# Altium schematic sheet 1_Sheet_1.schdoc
size 515 x 360 mm; Name: A_Customize; Symbol: A_Customize; Device: A_Customize; @Project Name: MyOwnMP3_PCB; REV: 1.0; Date: 2026-02-21; Sheet: 1/1; Draw By: maxyusyuk; Company: Your Company; Convert to PCB: yes; Add into BOM: yes; spicePre: .; @Page No: 1; @Page Count: 3; @Schematic Name: MyOwnMP3; @Board Name: MyOwnMP3; @Update Date: 2026-04-22; @Create Time: 17:18:59; @Update Time: 22:12:06; @Page Name: Sheet_1; @Create Date: 2026-03-28
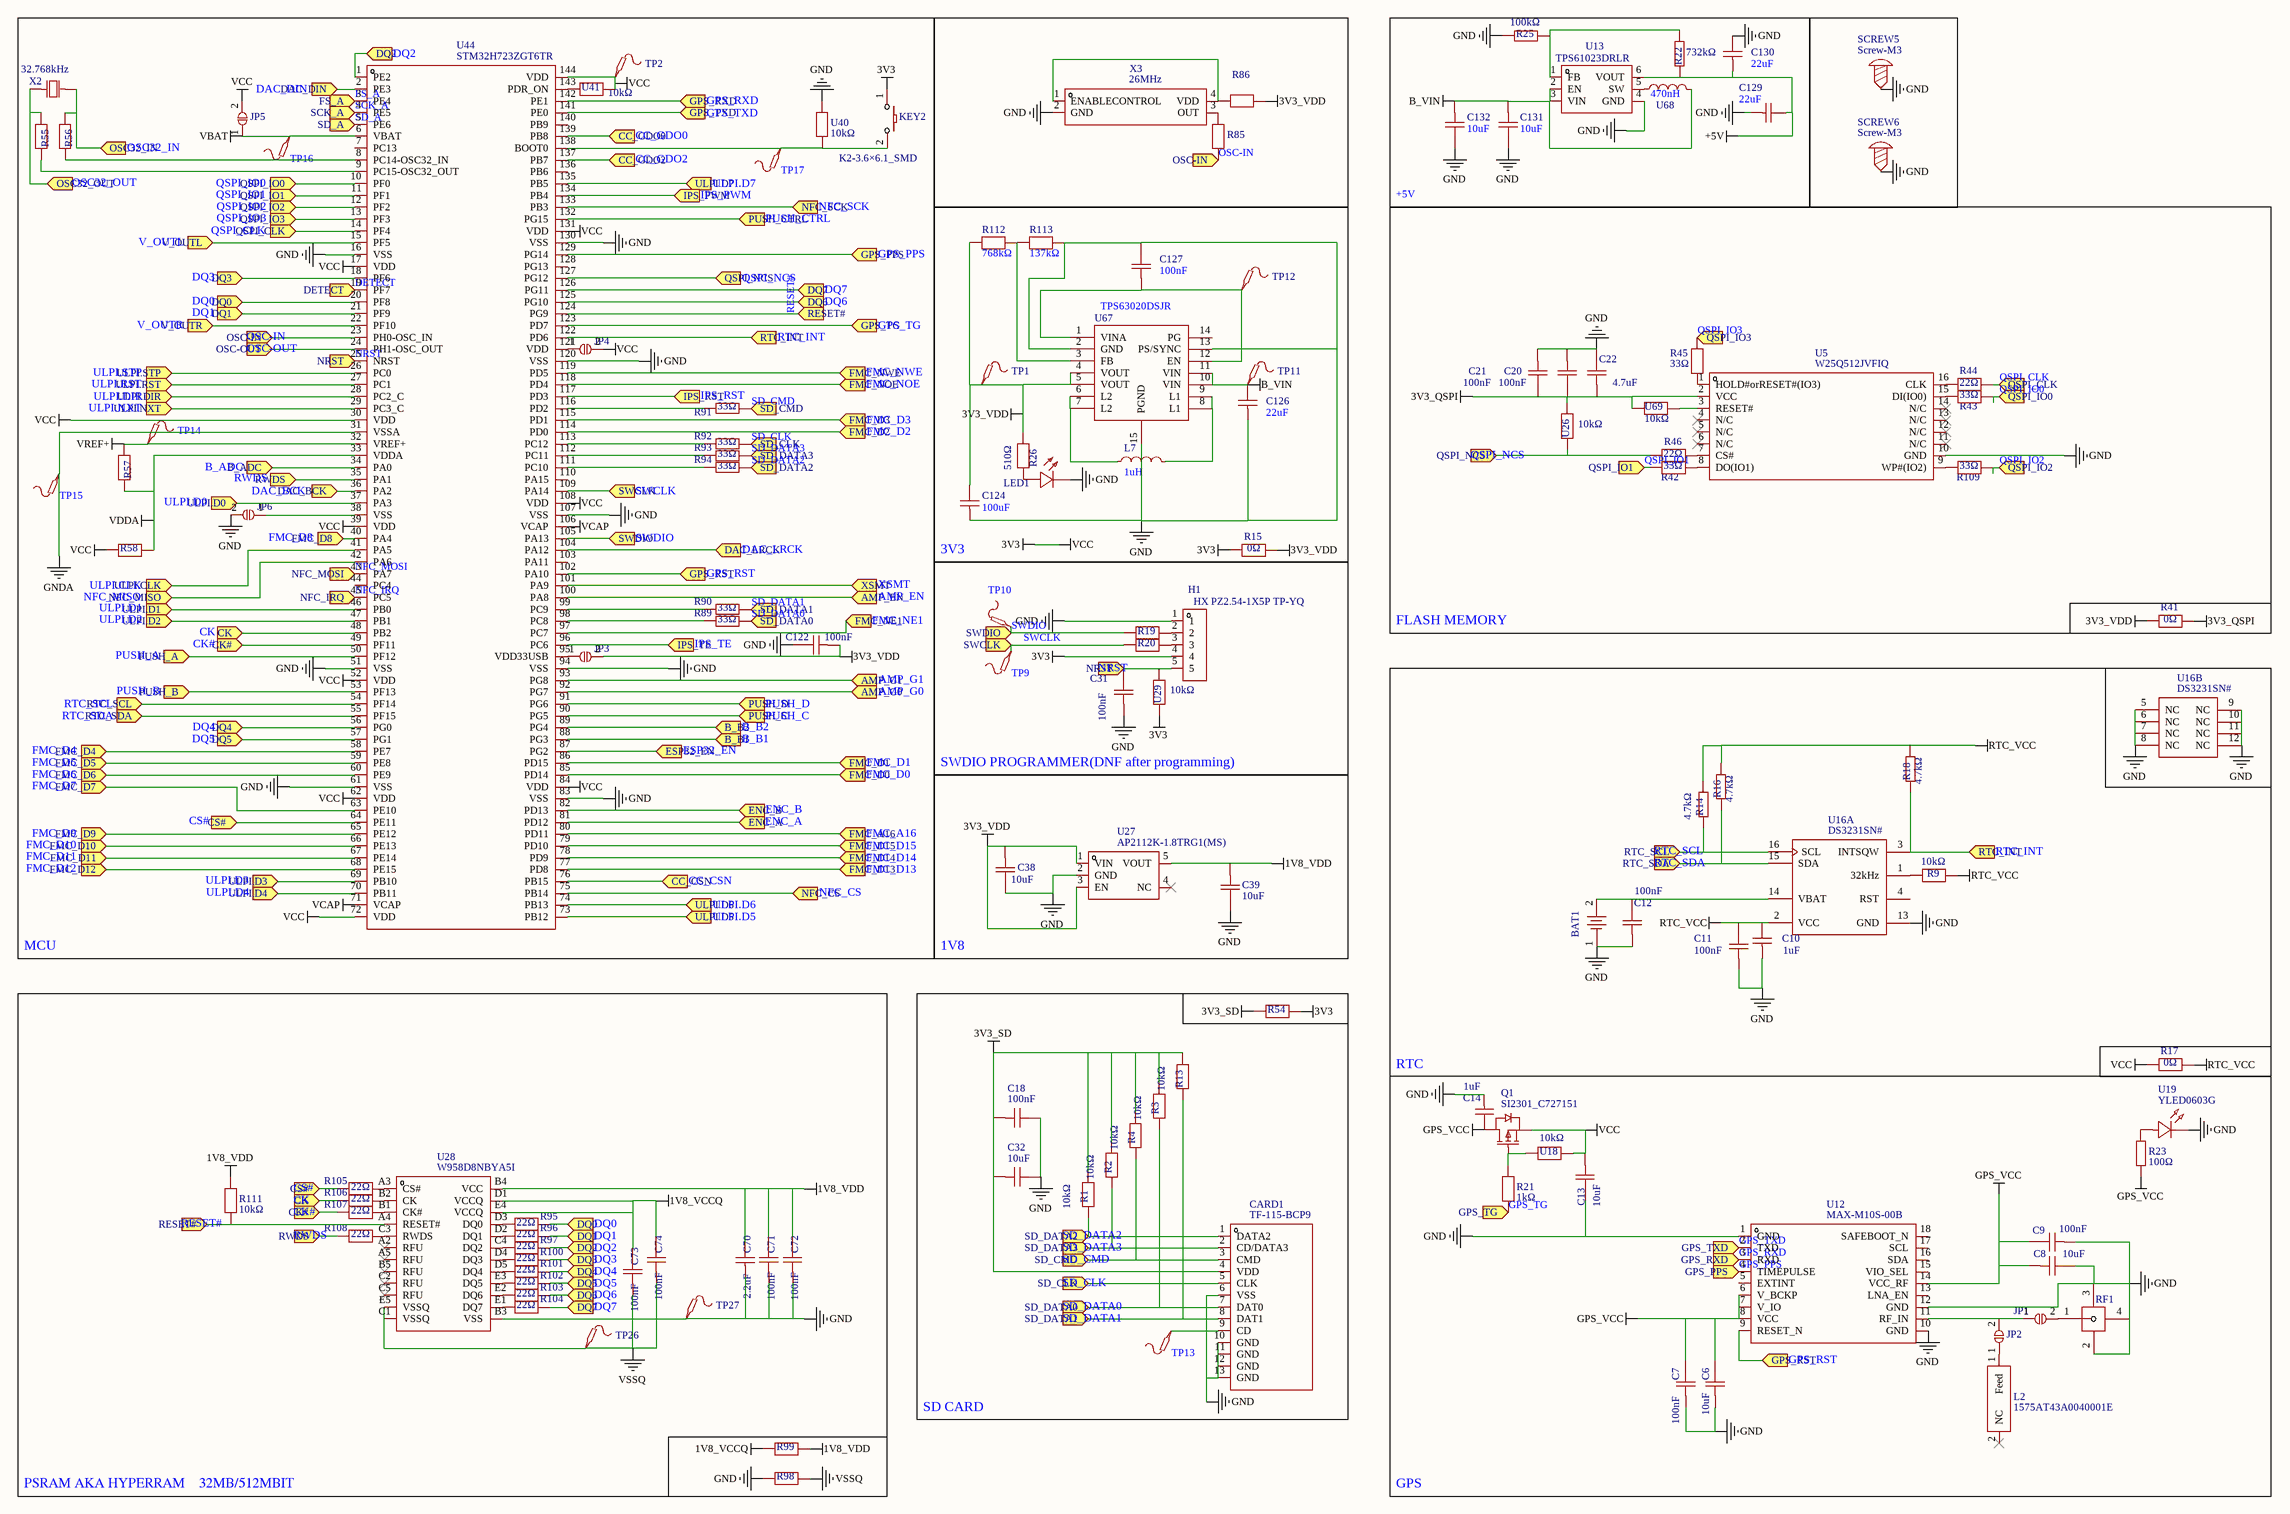
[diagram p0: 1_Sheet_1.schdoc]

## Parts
BAT1  BS-CR2032-8  [BAT-SMD_BS-CR2032-8]  (value not drawn)
C6  10uF  [C1206]
C7  100nF  [C0603]
C8  10uF  [C1206]
C9  100nF  [C0603]
C10  1uF  [C0603]
C11  100nF  [C0603]
C12  100nF  [C0603]
C13  10uF  [C1206]
C14  1uF  [C0603]
C18  100nF  [C0603]
C20  100nF  [C0603]
C21  100nF  [C0603]
C22  4.7uF  [C0603]
C31  100nF  [C0603]
C32  10uF  [C1206]
C38  10uF  [C1206]
C39  10uF  [C1206]
C70  2.2uF  [C0603]
C71  100nF  [C0603]
C72  100nF  [C0603]
C73  100nF  [C0603]
C74  100nF  [C0603]
C122  100nF  [C0603]
C124  100uF  [C1206]
C126  22uF  [C1206]
C127  100nF  [C0402]
C129  22uF  [C1206]
C130  22uF  [C1206]
C131  10uF  [C0805]
C132  10uF  [C0805]
CARD1  TF-115-BCP9  [TF-SMD_TF-115-BCP9]
H1  HX PZ2.54-1X5P TP-YQ  [HDR-SMD_5P--P2.54-V-M-S5.0_HX-PZ2.54-1X5P-TP-YQ]
JP1  2P Solder UNBridge Jumper  [SOLDER BRIDGE 2P UNBRIDGED]  (value not drawn)
JP2  2P Solder UNBridge Jumper  [SOLDER BRIDGE 2P UNBRIDGED]  (value not drawn)
JP3  2P Solder UNBridge Jumper  [SOLDER BRIDGE 2P UNBRIDGED]  (value not drawn)
JP4  2P Solder UNBridge Jumper  [SOLDER BRIDGE 2P UNBRIDGED]  (value not drawn)
JP5  2P Solder UNBridge Jumper  [SOLDER BRIDGE 2P UNBRIDGED]  (value not drawn)
JP6  2P Solder UNBridge Jumper  [SOLDER BRIDGE 2P UNBRIDGED]  (value not drawn)
KEY2  K2-3.6×6.1_SMD  [KEY-SMD_2P-L6.2-W3.6-LS8.0]
L2  1575AT43A0040001E  [ANT-SMD_L7.0-W2.0-R]
L7  1uH  [IND-SMD_L2.4-W2.4_NRH2410T]
LED1  YLED0603R  [LED0603-FD]  (value not drawn)
Q1  SI2301_C727151  [SOT-23-3_L2.9-W1.4-P1.91-LS2.6-BR]
R1  10kΩ  [R0603]
R2  10kΩ  [R0603]
R3  10kΩ  [R0603]
R4  10kΩ  [R0603]
R9  10kΩ  [R0603]
R13  10kΩ  [R0603]
R14  4.7kΩ  [R0603]
R15  0Ω  [R1206]
R16  4.7kΩ  [R0603]
R17  0Ω  [R1206]
R18  4.7kΩ  [R0603]
R19  0Ω  [R0603]  (value not drawn)
R20  0Ω  [R0603]  (value not drawn)
R21  1kΩ  [R0603]
R22  732kΩ  [R0603]
R23  100Ω  [R0603]
R25  100kΩ  [R1206]
R26  510Ω  [R0603]
R41  0Ω  [R1206]
R42  33Ω  [R0402]
R43  33Ω  [R0402]
R44  22Ω  [R0402]
R45  33Ω  [R0402]
R46  22Ω  [R0402]
R54  0Ω  [R0603]  (value not drawn)
R55  0Ω  [R0603]  (value not drawn)
R56  0Ω  [R0603]  (value not drawn)
R57  0Ω  [R0603]  (value not drawn)
R58  0Ω  [R0603]  (value not drawn)
R85  0Ω  [R0603]  (value not drawn)
R86  0Ω  [R0603]  (value not drawn)
R89  33Ω  [R0603]
R90  33Ω  [R0603]
R91  33Ω  [R0603]
R92  33Ω  [R0603]
R93  33Ω  [R0603]
R94  33Ω  [R0603]
R95  22Ω  [R0402]
R96  22Ω  [R0402]
R97  22Ω  [R0402]
R98  0Ω  [R0603]  (value not drawn)
R99  0Ω  [R0603]  (value not drawn)
R100  22Ω  [R0402]
R101  22Ω  [R0402]
R102  22Ω  [R0402]
R103  22Ω  [R0402]
R104  22Ω  [R0402]
R105  22Ω  [R0402]
R106  22Ω  [R0402]
R107  22Ω  [R0402]
R108  22Ω  [R0402]
R109  33Ω  [R0402]
R111  10kΩ  [R0603]
R112  768kΩ  [R0603]
R113  137kΩ  [R0402]
RF1  HC-RF-IPEX0303-01  [IPEX-SMD_HC-RF-IPEX0303-01]  (value not drawn)
SCREW5  Screw-M3  [SCREW-M3]
SCREW6  Screw-M3  [SCREW-M3]
TP1  (no value)  [Test-Point-0.5mm]
TP2  (no value)  [Test-Point-0.5mm]
TP9  (no value)  [Test-Point-0.5mm]
TP10  (no value)  [Test-Point-0.5mm]
TP11  (no value)  [Test-Point-0.5mm]
TP12  (no value)  [Test-Point-0.5mm]
TP13  (no value)  [Test-Point-0.5mm]
TP14  (no value)  [Test-Point-0.5mm]
TP15  (no value)  [Test-Point-0.5mm]
TP16  (no value)  [Test-Point-0.5mm]
TP17  (no value)  [Test-Point-0.5mm]
TP26  (no value)  [Test-Point-0.5mm]
TP27  (no value)  [Test-Point-0.5mm]
U5  W25Q512JVFIQ  [SOIC-16_L10.3-W7.5-P1.27-LS10.4-BL]
U12  MAX-M10S-00B  [SMD-18_L10.1-W9.7-P1.10-TL_SKG09F]
U13  TPS61023DRLR  [SOT-563_L1.6-W1.2-P0.50-LS1.6-BR]
U16  DS3231SN#  [SOIC-16_L10.3-W7.5-P1.27-LS10.3-BL]  (parts A,B of 2)
U18  10kΩ  [R0603]
U19  YLED0603G  [LED0603-FD]
U26  10kΩ  [R0603]
U27  AP2112K-1.8TRG1(MS)  [SOT-23-5_L2.9-W1.6-P0.95-LS2.8-BR]
U28  W958D8NBYA5I  [T-PBGA-24_L8.0-W6.0-P1.00-TL_MICRON_12]
U29  10kΩ  [R0603]
U40  10kΩ  [R0603]
U41  10kΩ  [R0603]
U44  STM32H723ZGT6TR  [LQFP-144_L20.0-W20.0-P0.50-LS22.0-BL]
U67  TPS63020DSJR  [VSON-14_L4.0-W3.0-P0.50-BL-EP_TI_DSJ]
U68  470nH  [IND-SMD_L2.0-W1.6]
U69  10kΩ  [R0603]
X2  32.768kHz  [OSC-SMD_L3.2-W1.5]
X3  26MHz  [OSC-SMD_4P-L5.0-W3.2-BL_SIT8103AI]

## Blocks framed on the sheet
MCU: C122 JP3-JP6 KEY2 R55-R58 R89-R94 TP2 TP14-TP17 U40 U41 U44 X2
+5V: C129-C132 R22 R25 U13 U68
3V3: C124 C126 C127 L7 LED1 R15 R26 R112 R113 TP1 TP11 TP12 U67
FLASH MEMORY: C20-C22 R41-R46 R109 U5 U26 U69
PSRAM AKA HYPERRAM  32MB/512MBIT: C70-C74 R95-R108 R111 TP26 TP27 U28
SD CARD: C18 C32 CARD1 R1-R4 R13 R54 TP13

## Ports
AMP_EN (in), AMP_G0 (in), AMP_G1 (in), B_ADC (in), B_B1 (in), B_B2 (in), CC_CSN (in), CC_GDO0 (in), CC_GDO2 (in), CK (in), CK# (in), CS# (in), DAC_BCK (in), DAC_DIN (in), DAC_LRCK (in), DETECT (in), DQ0 (in), DQ1 (in), DQ2 (in), DQ3 (in), DQ4 (in), DQ5 (in), DQ6 (in), DQ7 (in), ENC_A (in), ENC_B (in), ESP32_EN (in), FMC_A16 (in), FMC_D0 (in), FMC_D1 (in), FMC_D2 (in), FMC_D3 (in), FMC_D4 (in), FMC_D5 (in), FMC_D6 (in), FMC_D7 (in), FMC_D8 (in), FMC_D9 (in), FMC_D10 (in), FMC_D11 (in), FMC_D12 (in), FMC_D13 (in), FMC_D14 (in), FMC_D15 (in), FMC_NE1 (in), FMC_NOE (in), FMC_NWE (in), FS_A (in), GPS_PPS (in), GPS_RST (in), GPS_RXD (in), GPS_TG (in), GPS_TXD (in), IPS_PWM (in), IPS_RST (in), IPS_TE (in), NFC_CS (in), NFC_IRQ (in), NFC_MISO (in), NFC_MOSI (in), NFC_SCK (in), NRST (in), OSC32_IN (in), OSC32_OUT (in), OSC-IN (in), OSC-OUT (in), PUSH_A (in), PUSH_B (in), PUSH_C (in), PUSH_CTRL (in), PUSH_D (in), QSPI_CLK (in), QSPI_IO0 (in), QSPI_IO1 (in), QSPI_IO2 (in), QSPI_IO3 (in), QSPI_NCS (in), RESET# (in), RTC_INT (in), RTC_SCL (in), RTC_SDA (in), RWDS (in), SCK_A (in), SD_A (in), SD_CLK (in), SD_CMD (in), SD_DATA0 (in), SD_DATA1 (in), SD_DATA2 (in), SD_DATA3 (in), SWCLK (in), SWDIO (in), ULPI.CLK (in), ULPI.D0 (in), ULPI.D1 (in), ULPI.D2 (in), ULPI.D3 (in), ULPI.D4 (in), ULPI.D5 (in), ULPI.D6 (in), ULPI.D7 (in), ULPI.DIR (in), ULPI.NXT (in), ULPI.RST (in), ULPI.STP (in), V_OUTL (in), V_OUTR (in), XSMT (in)

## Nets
1V8_VCCQ: C73.1 C74.1 R99.2 U28.D1(VCCQ) U28.E4(VCCQ)
1V8_VDD: C39.2 C70.2 C71.1 C72.1 R99.1 R111.2 U27.5(VOUT) U28.B4(VCC)
3V3: C13.2 H1.4 JP4.2(B) JP5.2(B) KEY2.1 Q1.2(S) R15.1 R17.1 R54.1 R58.2 TP2.1 U18.2 U29.2 U41.2 U44.17(VDD) U44.30(VDD) U44.39(VDD) U44.52(VDD) U44.62(VDD) U44.72(VDD) U44.84(VDD) U44.108(VDD) U44.131(VDD) U44.144(VDD)  [also labelled VCC]
3V3_QSPI: C20.1 C21.1 C22.2 R41.2 U5.2(VCC) U26.1 U69.1
3V3_SD: C18.2 C32.2 CARD1.4(VDD) R1.2 R2.2 R3.2 R4.2 R13.2 R54.2
3V3_VDD: C38.2 C122.2 C124.2 JP3.2(B) R15.2 R26.1 R41.1 R86.2 R112.2 TP1.1 U27.1(VIN) U27.3(EN) U67.4(VOUT) U67.5(VOUT)
+5V: C129.2 C130.1 R22.1 U13.6(VOUT)
B_VIN: C126.2 C131.2 C132.2 TP11.1 U13.2(EN) U13.3(VIN) U67.10(VIN) U67.11(VIN) U68.2
GND: BAT1.1 C6.2 C7.2 C8.1 C9.2 C10.1 C11.2 C12.2 C13.1 C14.1 C18.1 C20.2 C21.2 C22.1 C31.2 C32.1 C38.1 C39.1 C70.1 C71.2 C72.2 C122.1 C124.1 C126.1 C127.1 C129.1 C130.2 C131.1 C132.1 CARD1.6(VSS) CARD1.10(GND) CARD1.11(GND) CARD1.12(GND) CARD1.13(GND) H1.1 JP6.2(B) LED1.2(-) R25.1 R98.2 R113.2 RF1.2 RF1.3 RF1.4 SCREW5.1 SCREW6.1 TP27.1 U5.10(GND) U12.1(GND) U12.10(GND) U12.12(GND) U13.4(GND) U16.5(NC) U16.6(NC) U16.7(NC) U16.8(NC) U16.9(NC) U16.10(NC) U16.11(NC) U16.12(NC) U16.13(GND) U19.2(-) U27.2(GND) U28.B3(VSS) U40.1 U44.16(VSS) U44.51(VSS) U44.61(VSS) U44.83(VSS) U44.94(VSS) U44.107(VSS) U44.120(VSS) U44.130(VSS) U67.2(GND) U67.13(PS/SYNC) U67.15(PGND) X3.2(GND)
GNDA: TP15.1 U44.31(VSSA)
GPS_VCC: C6.1 C7.1 C8.2 C9.1 C14.2 Q1.3(D) R23.1 U12.6(V_BCKP) U12.7(V_IO) U12.8(VCC) U12.14(VCC_RF)
RTC_VCC: C10.2 C11.1 R9.1 R14.2 R16.2 R17.2 R18.2 U16.2(VCC)
VBAT: JP5.1(A) TP16.1 U44.6(VBAT)
VCAP: U44.71(VCAP) U44.106(VCAP)
VDDA: R57.1 R58.1 U44.33(VDDA)
VREF+: R57.2 TP14.1 U44.32(VREF+)
VSSQ: C73.2 C74.2 R98.1 TP26.1 U28.C1(VSSQ) U28.E5(VSSQ)
AMP_EN: U44.100(PA8) ; port AMP_EN
AMP_G0: U44.92(PG7) ; port AMP_G0
AMP_G1: U44.93(PG8) ; port AMP_G1
B_ADC: U44.34(PA0) ; port B_ADC
B_B1: U44.88(PG3) ; port B_B1
B_B2: U44.89(PG4) ; port B_B2
CC_CSN: U44.76(PB15) ; port CC_CSN
CC_GDO0: U44.139(PB8) ; port CC_GDO0
CC_GDO2: U44.137(PB7) ; port CC_GDO2
CK: R106.1 U44.48(PB2) ; port CK
CK#: R107.1 U44.49(PF11) ; port CK#
CS#: R105.1 U44.64(PE11) ; port CS#
DAC_BCK: U44.36(PA2) ; port DAC_BCK
DAC_DIN: U44.2(PE3) ; port DAC_DIN
DAC_LRCK: U44.104(PA12) ; port DAC_LRCK
DETECT: U44.19(PF7) ; port DETECT
DQ0: R95.2 U44.20(PF8) ; port DQ0
DQ1: R96.2 U44.21(PF9) ; port DQ1
DQ2: R97.2 U44.1(PE2) ; port DQ2
DQ3: R100.2 U44.18(PF6) ; port DQ3
DQ4: R101.2 U44.56(PG0) ; port DQ4
DQ5: R102.2 U44.57(PG1) ; port DQ5
DQ6: R103.2 U44.125(PG10) ; port DQ6
DQ7: R104.2 U44.126(PG11) ; port DQ7
ENC_A: U44.81(PD12) ; port ENC_A
ENC_B: U44.82(PD13) ; port ENC_B
ESP32_EN: U44.87(PG2) ; port ESP32_EN
FMC_A16: U44.80(PD11) ; port FMC_A16
FMC_D0: U44.85(PD14) ; port FMC_D0
FMC_D1: U44.86(PD15) ; port FMC_D1
FMC_D2: U44.114(PD0) ; port FMC_D2
FMC_D3: U44.115(PD1) ; port FMC_D3
FMC_D4: U44.58(PE7) ; port FMC_D4
FMC_D5: U44.59(PE8) ; port FMC_D5
FMC_D6: U44.60(PE9) ; port FMC_D6
FMC_D7: U44.63(PE10) ; port FMC_D7
FMC_D8: U44.40(PA4) ; port FMC_D8
FMC_D9: U44.65(PE12) ; port FMC_D9
FMC_D10: U44.66(PE13) ; port FMC_D10
FMC_D11: U44.67(PE14) ; port FMC_D11
FMC_D12: U44.68(PE15) ; port FMC_D12
FMC_D13: U44.77(PD8) ; port FMC_D13
FMC_D14: U44.78(PD9) ; port FMC_D14
FMC_D15: U44.79(PD10) ; port FMC_D15
FMC_NE1: U44.97(PC7) ; port FMC_NE1
FMC_NOE: U44.118(PD4) ; port FMC_NOE
FMC_NWE: U44.119(PD5) ; port FMC_NWE
FS_A: U44.3(PE4) ; port FS_A
GPS_PPS: U12.4(TIMEPULSE) U44.129(PG14) ; port GPS_PPS
GPS_RST: U12.9(RESET_N) U44.102(PA10) ; port GPS_RST
GPS_RXD: U12.3(RXD) U44.142(PE1) ; port GPS_RXD
GPS_TG: R21.1 U44.123(PD7) ; port GPS_TG
GPS_TXD: U12.2(TXD) U44.141(PE0) ; port GPS_TXD
IPS_PWM: U44.134(PB4) ; port IPS_PWM
IPS_RST: U44.117(PD3) ; port IPS_RST
IPS_TE: U44.96(PC6) ; port IPS_TE
NFC_CS: U44.75(PB14) ; port NFC_CS
NFC_IRQ: U44.45(PC5) ; port NFC_IRQ
NFC_MISO: U44.42(PA6) ; port NFC_MISO
NFC_MOSI: U44.43(PA7) ; port NFC_MOSI
NFC_SCK: U44.133(PB3) ; port NFC_SCK
NRST: C31.1 H1.5 U29.1 U44.25(NRST) ; port NRST
OSC32_IN: R56.2 X2.2(OSC2) ; port OSC32_IN
OSC32_OUT: R55.2 X2.1(OSC1) ; port OSC32_OUT
OSC-IN: R85.2 U44.23(PH0-OSC_IN) ; port OSC-IN
OSC-OUT: U44.24(PH1-OSC_OUT) ; port OSC-OUT
PUSH_A: U44.50(PF12) ; port PUSH_A
PUSH_B: U44.53(PF13) ; port PUSH_B
PUSH_C: U44.90(PG5) ; port PUSH_C
PUSH_CTRL: U44.132(PG15) ; port PUSH_CTRL
PUSH_D: U44.91(PG6) ; port PUSH_D
QSPI_CLK: R44.2 U44.14(PF4) ; port QSPI_CLK
QSPI_IO0: R43.2 U44.10(PF0) ; port QSPI_IO0
QSPI_IO1: R42.1 U44.11(PF1) ; port QSPI_IO1
QSPI_IO2: R109.2 U44.12(PF2) ; port QSPI_IO2
QSPI_IO3: R45.1 U44.13(PF3) ; port QSPI_IO3
QSPI_NCS: R46.1 U26.2 U44.127(PG12) ; port QSPI_NCS
RESET#: R111.1 U28.A4(RESET#) U44.124(PG9) ; port RESET#
RTC_INT: R18.1 U16.3(INTSQW) U44.122(PD6) ; port RTC_INT
RTC_SCL: R14.1 U16.16(SCL) U44.54(PF14) ; port RTC_SCL
RTC_SDA: R16.1 U16.15(SDA) U44.55(PF15) ; port RTC_SDA
RWDS: R108.1 U44.35(PA1) ; port RWDS
SCK_A: U44.4(PE5) ; port SCK_A
SD_A: U44.5(PE6) ; port SD_A
SD_CLK: CARD1.5(CLK) R92.2 ; port SD_CLK
SD_CMD: CARD1.3(CMD) R4.1 R91.2 ; port SD_CMD
SD_DATA0: CARD1.7(DAT0) R3.1 R89.2 ; port SD_DATA0
SD_DATA1: CARD1.8(DAT1) R13.1 R90.2 ; port SD_DATA1
SD_DATA2: CARD1.1(DATA2) R1.1 R94.2 ; port SD_DATA2
SD_DATA3: CARD1.2(CD/DATA3) R2.1 R93.2 ; port SD_DATA3
SWCLK: R20.1 TP9.1 U44.109(PA14) ; port SWCLK
SWDIO: R19.1 TP10.1 U44.105(PA13) ; port SWDIO
ULPI.CLK: U44.41(PA5) ; port ULPI.CLK
ULPI.D0: U44.37(PA3) ; port ULPI.D0
ULPI.D1: U44.46(PB0) ; port ULPI.D1
ULPI.D2: U44.47(PB1) ; port ULPI.D2
ULPI.D3: U44.69(PB10) ; port ULPI.D3
ULPI.D4: U44.70(PB11) ; port ULPI.D4
ULPI.D5: U44.73(PB12) ; port ULPI.D5
ULPI.D6: U44.74(PB13) ; port ULPI.D6
ULPI.D7: U44.135(PB5) ; port ULPI.D7
ULPI.DIR: U44.28(PC2_C) ; port ULPI.DIR
ULPI.NXT: U44.29(PC3_C) ; port ULPI.NXT
ULPI.RST: U44.27(PC1) ; port ULPI.RST
ULPI.STP: U44.26(PC0) ; port ULPI.STP
V_OUTL: U44.15(PF5) ; port V_OUTL
V_OUTR: U44.22(PF10) ; port V_OUTR
XSMT: U44.101(PA9) ; port XSMT
NetBAT1_2: BAT1.2 C12.1 U16.14(VBAT)
NetC127_2: C127.2 TP12.1 U67.1(VINA) U67.12(EN)
NetCARD1_9: CARD1.9(CD) TP13.1
NetH1_2: H1.2 R19.2
NetH1_3: H1.3 R20.2
NetJP1_1: JP1.1(A) JP2.2(B) U12.11(RF_IN)
NetJP1_2: JP1.2(B) RF1.1
NetJP2_1: JP2.1(A) L2.1(Feed)
NetJP3_1: JP3.1(A) U44.95(VDD33USB)
NetJP4_1: JP4.1(A) U44.121(VDD)
NetJP6_1: JP6.1(A) U44.38(VSS)
NetKEY2_2: KEY2.2 TP17.1 U40.2 U44.138(BOOT0)
NetL7_1: L7.1 U67.6(L2) U67.7(L2)
NetL7_2: L7.2 U67.8(L1) U67.9(L1)
NetLED1_1: LED1.1(+) R26.2
NetQ1_1: Q1.1(G) R21.2 U18.1
NetR9_2: R9.2 U16.1(32kHz)
NetR22_2: R22.2 R25.2 U13.1(FB)
NetR23_2: R23.2 U19.1(+)
NetR42_2: R42.2 U5.8(DO(IO1))
NetR43_1: R43.1 U5.15(DI(IO0))
NetR44_1: R44.1 U5.16(CLK)
NetR45_2: R45.2 U5.1(HOLD#orRESET#(IO3))
NetR46_2: R46.2 U5.7(CS#)
NetR55_1: R55.1 U44.9(PC15-OSC32_OUT)
NetR56_1: R56.1 U44.8(PC14-OSC32_IN)
NetR85_1: R85.1 X3.3(OUT)
NetR86_1: R86.1 X3.1(ENABLECONTROL) X3.4(VDD)
NetR89_1: R89.1 U44.98(PC8)
NetR90_1: R90.1 U44.99(PC9)
NetR91_1: R91.1 U44.116(PD2)
NetR92_1: R92.1 U44.113(PC12)
NetR93_1: R93.1 U44.112(PC11)
NetR94_1: R94.1 U44.111(PC10)
NetR95_1: R95.1 U28.D3(DQ0)
NetR96_1: R96.1 U28.D2(DQ1)
NetR97_1: R97.1 U28.C4(DQ2)
NetR100_1: R100.1 U28.D4(DQ3)
NetR101_1: R101.1 U28.D5(DQ4)
NetR102_1: R102.1 U28.E3(DQ5)
NetR103_1: R103.1 U28.E2(DQ6)
NetR104_1: R104.1 U28.E1(DQ7)
NetR105_2: R105.2 U28.A3(CS#)
NetR106_2: R106.2 U28.B2(CK)
NetR107_2: R107.2 U28.B1(CK#)
NetR108_2: R108.2 U28.C3(RWDS)
NetR109_1: R109.1 U5.9(WP#(IO2))
NetR112_1: R112.1 R113.1 U67.3(FB)
NetU5_3: U5.3(RESET#) U69.2
NetU13_5: U13.5(SW) U68.1
NetU41_1: U41.1 U44.143(PDR_ON)

Not connected (* = marked no-connect by the designer): L2 2(NC)*; U5 4(N/C)* 5(N/C)* 6(N/C)* 11(N/C)* 12(N/C)* 13(N/C)* 14(N/C)*; U12 5(EXTINT) 13(LNA_EN) 15(VIO_SEL) 16(SDA) 17(SCL) 18(SAFEBOOT_N); U16 4(RST); U27 4(NC)*; U28 A2(RFU)* A5(RFU)* B5(RFU)* C2(RFU)* C5(RFU)*; U44 7(PC13) 44(PC4) 103(PA11) 110(PA15) 128(PG13) 136(PB6) 140(PB9); U67 14(PG)

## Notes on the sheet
- SWDIO PROGRAMMER(DNF after programming)
- 1V8
- RTC
- GPS
- Labels drawn without touching a wire or pin: AMP_EN, AMP_G0, AMP_G1, B_ADC, B_B1, B_B2, CC_CSN, CC_GDO0, CC_GDO2, CK, CK#, CS#, DAC_BCK, DAC_DIN, DAC_LRCK, DQ0, DQ1, DQ2, DQ3, DQ4, DQ5, DQ6, DQ7, ENC_A, ENC_B, ESP32_EN, FMC_A16, FMC_D0, FMC_D1, FMC_D2, FMC_D3, FMC_D4, FMC_D5, FMC_D6, FMC_D7, FMC_D8, FMC_D9, FMC_D10, FMC_D11, FMC_D12, FMC_D13, FMC_D14, FMC_D15, FMC_NE1, FMC_NOE, FMC_NWE, GPS_PPS, GPS_RST, GPS_RXD, GPS_TG, GPS_TXD, IPS_PWM, IPS_RST, IPS_TE, NFC_CS, NFC_MISO, NFC_SCK, NRST, OSC32_IN, OSC32_OUT, OSC-IN, OSC-OUT, PUSH_A, PUSH_B, PUSH_C, PUSH_CTRL, PUSH_D, QSPI_CLK, QSPI_IO0, QSPI_IO1, QSPI_IO2, QSPI_IO3, QSPI_NCS, RESET#, RTC_INT, RTC_SCL, RTC_SDA, RWDS, SD_CLK, SD_CMD, SD_DATA0, SD_DATA1, SD_DATA2, SD_DATA3, SWCLK, SWDIO, ULPI.CLK, ULPI.D0, ULPI.D1, ULPI.D2, ULPI.D3, ULPI.D4, ULPI.D5, ULPI.D6, ULPI.D7, ULPI.DIR, ULPI.NXT, ULPI.RST, ULPI.STP, V_OUTL, V_OUTR, XSMT

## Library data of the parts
BAT1 = BS-CR2032-8: Manufacturer: LX(连欣科技); Convert to PCB: yes; Contributor: lcsc
C6 C8 C13 C32 C38 C39 = 10uF: Manufacturer: CCTC(三环); Manufacturer Part: TCC1206X7R106K160HT; Convert to PCB: yes; nameAlias: Value; Contributor: LCSC
C7 C9 C11 C12 C20 C21 C31 C122 = 100nF: Manufacturer: YAGEO(国巨); Manufacturer Part: CC0603JRX7R8BB104; Convert to PCB: yes; nameAlias: Value; Contributor: LCSC
C10 C14 = 1uF: Manufacturer Part: CC0603KRX5R8BB105; Manufacturer: YAGEO(国巨); Convert to PCB: yes; nameAlias: Value
C18 C71-C74 = 100nF: Manufacturer: YAGEO(国巨); Manufacturer Part: AC0603KRX7R0BB104; Convert to PCB: yes; nameAlias: Value; Contributor: LCSC
C22 = 4.7uF: Manufacturer: CCTC(三环); Manufacturer Part: TCC0603X5R475K100CT; Convert to PCB: yes; nameAlias: Value; Contributor: LCSC
C70 = 2.2uF: Manufacturer: YAGEO(国巨); Manufacturer Part: CC0603KRX5R7BB225; Convert to PCB: yes; nameAlias: Value
C124 = CL31A107MQHNNNE: Manufacturer: SAMSUNG(三星); Add into BOM: yes; Tolerance: ±20%; Voltage Rating: 6.3V; Temperature Coefficient: X5R
C126 C129 C130 = CL31A226KAHNNNE: Manufacturer: SAMSUNG(三星); Add into BOM: yes; Tolerance: ±10%; Voltage Rating: 25V; Temperature Coefficient: X5R
C127 = CL05B104KO5NNNC: Manufacturer: SAMSUNG(三星); Add into BOM: yes; Tolerance: ±10%; Voltage Rating: 16V; Temperature Coefficient: X7R
C131 C132 = CL21A106KAYNNNE_C15850: Manufacturer: SAMSUNG(三星); Add into BOM: yes; Tolerance: ±10%; Voltage Rating: 25V; Temperature Coefficient: X5R
CARD1 = TF-115-BCP9: Manufacturer: XUNPU(讯普); Convert to PCB: yes; Contributor: LCSC
H1 = HX PZ2.54-1X5P TP-YQ: Manufacturer: hanxia(韩下); Convert to PCB: yes; Contributor: lcsc
JP1-JP6 = 2P Solder UNBridge Jumper: Manufacturer Part: DNP; Convert to PCB: yes; Add into BOM: no; Contributor: RonNovy
KEY2 = K2-3.6×6.1_SMD: Manufacturer Part: K2-1107ST-A4SW-06; 制造商: 韩国韩荣; Convert to PCB: yes; Contributor: LCEDA_Lib
L2 = 1575AT43A0040001E: Manufacturer: JOHANSON(约翰逊); Convert to PCB: yes; Contributor: lcsc
L7 = ASPI-2410-1R0N-T2: Manufacturer: ABRACON; Add into BOM: yes; Tolerance: ±30%; Current Rating: 1.9A; Current - Saturation(Isat): 2A; DC Resistance(DCR): 70mΩ; Type: Magnetic Shielded Inductor
LED1 = YLED0603R: Manufacturer: YONGYUTAI(永裕泰); Convert to PCB: yes; Contributor: lcsc
Q1 = SI2301_C727151: Manufacturer: TWGMC(迪嘉); Manufacturer Part: SI2301; Convert to PCB: yes; Contributor: LCSC
R1-R4 R9 R13 R111 = 10kΩ: Manufacturer: VO(翔胜); Manufacturer Part: SCR0603J10K; Convert to PCB: yes; nameAlias: Value; Contributor: lcsc
R14 R16 R18 = 4.7kΩ: Manufacturer: UNI-ROYAL(厚声); Manufacturer Part: 0603WAF4701T5E; Convert to PCB: yes; nameAlias: Value
R15 R17 R41 = 0Ω: Manufacturer: JIERR(捷而瑞); Manufacturer Part: JER1206F1R000; Convert to PCB: yes; nameAlias: Value; Contributor: lcsc
R19 R20 R54-R58 R85 R86 R98 R99 = 0Ω: Manufacturer: Walsin(华新科); Manufacturer Part: WR06X000 PTL; Convert to PCB: yes; nameAlias: Value; Contributor: lcsc
R21 = 1kΩ: Manufacturer: UNI-ROYAL(厚声); Manufacturer Part: TC0325B1001T5F; Convert to PCB: yes; nameAlias: Value; Contributor: lcsc
R22 = 732kΩ: Manufacturer: YAGEO(国巨); Manufacturer Part: RC0603FR-07732KL; Convert to PCB: yes; nameAlias: Value; Contributor: LCSC
R23 = 100Ω: Manufacturer: YAGEO(国巨); Manufacturer Part: AF0603FR-07100RL; Convert to PCB: yes; nameAlias: Value; Contributor: LCSC
R25 = 100kΩ: Manufacturer: YAGEO(国巨); Manufacturer Part: RT1206FRD07100KL; Convert to PCB: yes; nameAlias: Value; Contributor: LCSC
R26 = 510Ω: Manufacturer: FOJAN(富捷); Manufacturer Part: FRC0603F5100TS; Convert to PCB: yes; nameAlias: Value; Contributor: lcsc
R42 R43 R45 R109 = 33Ω: Manufacturer: FOJAN(富捷); Manufacturer Part: FRC0402F33R0TS; Convert to PCB: yes; nameAlias: Value; Contributor: lcsc
R44 R46 R95-R97 R100-R108 = 22Ω: Manufacturer: FOJAN(富捷); Manufacturer Part: FRC0402J220 TS; Convert to PCB: yes; nameAlias: Value; Contributor: lcsc
R89-R94 = 33Ω: Manufacturer: LIZ(丽智电子); Manufacturer Part: CR0603JA0330G; Convert to PCB: yes; nameAlias: Value
R112 = FRC0603F7683TS: Manufacturer: FOJAN(富捷); Add into BOM: yes; Tolerance: ±1%; Power(Watts): 100mW; Voltage-Supply(Max): 75V; Temperature Coefficient: ±100ppm/℃
R113 = FRC0402F1373TS: Manufacturer: FOJAN(富捷); Add into BOM: yes; Tolerance: ±1%; Power(Watts): 62.5mW; Voltage-Supply(Max): 50V; Temperature Coefficient: ±100ppm/℃
RF1 = HC-RF-IPEX0303-01: Manufacturer: HCTL(华灿天禄); Convert to PCB: yes; Contributor: LCSC
SCREW5 SCREW6 = Screw-M3: Convert to PCB: yes; Contributor: EasyEDA
TP1 TP2 TP9-TP17 TP26 TP27 = Test-Point: Add into BOM: no; Convert to PCB: yes
U5 = W25Q512JVFIQ: Manufacturer: Winbond(华邦); Convert to PCB: yes; Contributor: LCSC
U12 = MAX-M10S-00B: Manufacturer: U-BLOX; Convert to PCB: yes; Contributor: lcsc
U13 = TPS61023DRLR: Manufacturer: TI(德州仪器); Convert to PCB: yes; Contributor: LCSC
U16 = DS3231SN#: Manufacturer: ADI(亚德诺)/MAXIM(美信); Manufacturer Part: DS3231SN#T&R; subpart_no: 1; tags: Clock; Convert to PCB: yes
U18 U26 U29 U40 U41 U69 = 10kΩ: Manufacturer: RESI(开步睿思); Manufacturer Part: PTFR0603B10K0N9; Convert to PCB: yes; nameAlias: Value; Contributor: lcsc
U19 = YLED0603G: Manufacturer: YONGYUTAI(永裕泰); Convert to PCB: yes; Contributor: lcsc
U27 = AP2112K-1.8TRG1(MS): Manufacturer: MSKSEMI(美森科); Convert to PCB: yes; Contributor: lcsc
U28 = W958D8NBYA5I: Manufacturer: Winbond(华邦); Convert to PCB: yes; Contributor: lcsc
U44 = STM32H723ZGT6TR: Manufacturer: ST(意法半导体); Convert to PCB: yes; Contributor: lcsc
U67 = TPS63020DSJR: Manufacturer: TI(德州仪器); Add into BOM: yes; Function: Boost type; Output Type: Adjustable; Voltage - Supply: 1.8V~5.5V; Output Voltage: 1.2V~5.5V; Output Current: 3A; Frequency - Switching: 2.4MHz; Number of Outputs: 1; Topology: Step-down-Boost; Quiescent Current: 50uA; Switch tube (built-in/external): Built-in
U68 = YSMC2016S-R47M: Manufacturer: YJYCOIN(益嘉源); Add into BOM: yes; Tolerance: ±20%
X2 = 32.768kHz: Manufacturer: NDK; Manufacturer Part: NX3215SA-32.768K-STD-MUA-14; Convert to PCB: yes; nameAlias: Value; Contributor: LCSC
X3 = 26MHz: Manufacturer: JGHC(晶光华); Manufacturer Part: O5326000153350; Convert to PCB: yes; Contributor: LCSC; nameAlias: Value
